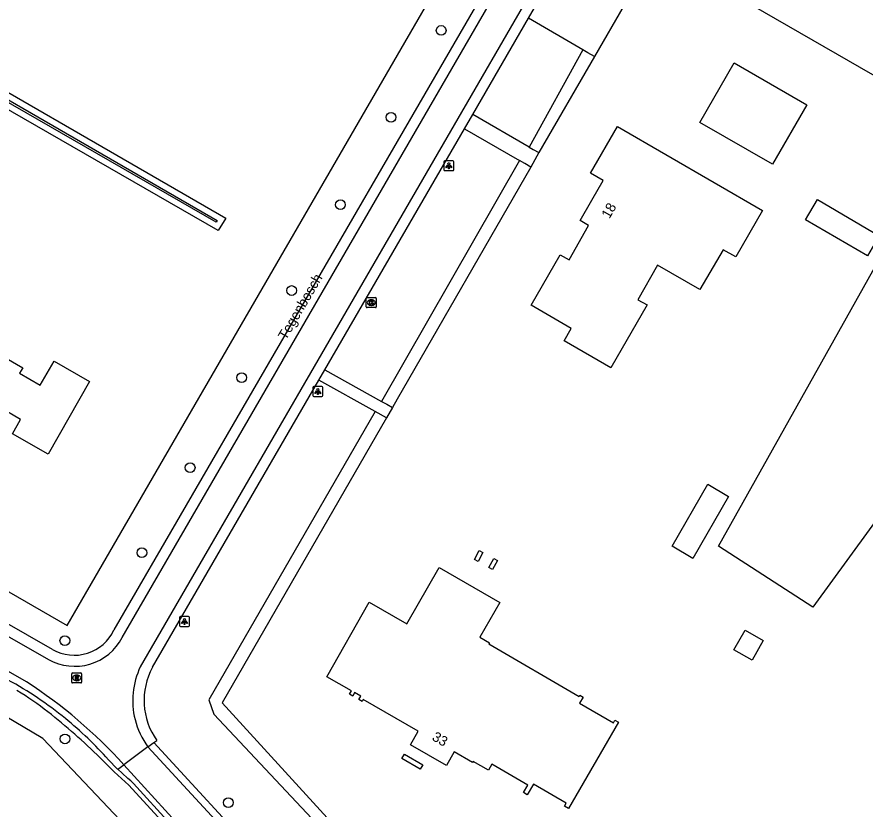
# Model space of a CAD drawing. Extents: x 156502 to 159074, y 384229 to 386094.
# Drawn here: x 157152.4 to 157237.7, y 385707.8 to 385787.5 of the extents above; entities that cross this region are included whole.
import ezdxf

# ---------------------------------------------------------------- set-up
doc = ezdxf.new("R2010")
doc.units = 0
for name, color, linetype in [('IMGEO_Berm_groen', 7, 'Continuous'), ('IMGEO_Berm_open', 7, 'Continuous'), ('IMGEO_Boom', 7, 'Continuous'), ('IMGEO_Erf', 7, 'Continuous'), ('IMGEO_Gemengd_bos', 7, 'Continuous'), ('IMGEO_Grasland_overig', 7, 'Continuous'), ('IMGEO_Groenvoorziening', 7, 'Continuous'), ('IMGEO_Hek', 7, 'Continuous'), ('IMGEO_Kolk', 7, 'Continuous'), ('IMGEO_Lichtpunt', 7, 'Continuous'), ('IMGEO_Openbare_ruimte_label', 7, 'Continuous'), ('IMGEO_Pand', 7, 'Continuous'), ('IMGEO_Pand_nummerreeks', 7, 'Continuous'), ('IMGEO_Rijbaan_lokaal_gesloten', 7, 'Continuous'), ('IMGEO_Rijbaan_lokaal_halfverhard', 7, 'Continuous'), ('IMGEO_Rijbaan_lokaal_open', 7, 'Continuous'), ('IMGEO_Rioolput', 7, 'Continuous'), ('IMGEO_Voetpad_open', 7, 'Continuous'), ('IMGEO_Waterloop', 7, 'Continuous')]:
    doc.layers.add(name, color=color, linetype=linetype)

msp = doc.modelspace()

# ---------------------------------------------------------------- linework, layer by layer
at = {"layer": 'IMGEO_Berm_groen'}
msp.add_lwpolyline([(157149.855, 385730.69), (157157.489, 385726.3), (157201.732, 385802.693)], dxfattribs=at)
at = {"layer": 'IMGEO_Berm_open'}
msp.add_lwpolyline([(157165.011, 385703.658), (157167.069, 385705.548), (157167.262, 385706.33), (157166.599, 385707.057), (157163.676, 385710.253), (157162.212, 385711.565), (157160.802, 385712.985)], dxfattribs=at)
for centre, radius, start, end in [((157139.852, 385698.063), 25.067, 51.20506, 59.86057), ((157114.204, 385665.314), 66.663, 45.65222, 51.65962)]:
    msp.add_arc(centre, radius, start, end, dxfattribs=at)
at = {"layer": 'IMGEO_Boom'}
for centre in [(157195.082, 385786.106), (157190.045, 385777.377), (157184.958, 385768.592), (157180.048, 385759.963), (157175.016, 385751.204), (157169.847, 385742.161), (157164.994, 385733.609), (157157.253, 385724.77), (157157.263, 385714.892), (157173.691, 385708.485)]:
    msp.add_circle(centre, 0.489, dxfattribs=at)
at = {"layer": 'IMGEO_Erf'}
msp.add_lwpolyline([(157069.688, 385879.771), (157062.244, 385869.451), (157047.224, 385849.55), (157042.786, 385843.67), (157065.314, 385829.887), (157068.346, 385827.983), (157173.435, 385767.228), (157172.677, 385766.006), (157064.372, 385828.327), (157041.356, 385841.775), (157036.588, 385835.458)], dxfattribs=at)
at = {"layer": 'IMGEO_Gemengd_bos'}
msp.add_lwpolyline([(157300.611, 385725.628), (157250.886, 385753.432), (157232.436, 385728.117), (157222.966, 385734.271), (157242.958, 385769.961), (157246.925, 385776.791)], dxfattribs=at)
at = {"layer": 'IMGEO_Grasland_overig'}
msp.add_lwpolyline([(157246.925, 385776.791), (157216.71, 385794.202)], dxfattribs=at)
at = {"layer": 'IMGEO_Groenvoorziening'}
for points in [[(157209.322, 385784.15), (157203.918, 385774.387)], [(157210.483, 385783.472), (157204.894, 385773.824)], [(157202.954, 385773.026), (157189.099, 385748.819)], [(157204.086, 385772.373), (157190.66, 385749.032), (157190.191, 385748.219)], [(157188.458, 385747.796), (157171.716, 385718.804), (157172.234, 385717.388), (157187.763, 385700.816)], [(157189.585, 385747.166), (157173.064, 385718.503), (157188.558, 385701.554)], [(157165.17, 385704.25), (157155.054, 385714.92), (157136.059, 385726.15)]]:
    msp.add_lwpolyline(points, dxfattribs=at)
at = {"layer": 'IMGEO_Hek'}
msp.add_lwpolyline([(157149.855, 385730.69), (157157.489, 385726.3), (157201.732, 385802.693)], dxfattribs=at)
at = {"layer": 'IMGEO_Kolk'}
for p, q in [((157187.556, 385758.32), (157187.556, 385759.172)), ((157187.631, 385759.246), (157188.483, 385759.246)), ((157188.044, 385759.026), (157188.069, 385759.026)), ((157188.557, 385759.172), (157188.557, 385758.32)), ((157188.483, 385758.246), (157187.631, 385758.246)), ((157188.067, 385758.466), (157188.042, 385758.466))]:
    msp.add_line(p, q, dxfattribs=at)
for points in [[(157187.556, 385758.32), (157187.556, 385759.172)], [(157187.631, 385759.246), (157188.483, 385759.246)], [(157187.877, 385758.946), (157188, 385758.946), (157188, 385758.795), (157188.13, 385758.946), (157188.294, 385758.946), (157188.148, 385758.795), (157188.301, 385758.546), (157188.149, 385758.546), (157188.064, 385758.71), (157188, 385758.643), (157188, 385758.546), (157187.877, 385758.546), (157187.877, 385758.946)], [(157188.557, 385759.172), (157188.557, 385758.32)], [(157188.483, 385758.246), (157187.631, 385758.246)]]:
    msp.add_lwpolyline(points, dxfattribs=at)
for centre, start, end in [((157187.633, 385759.17), 91.55205, 178.44795), ((157187.633, 385759.17), 91.55205, 178.44795), ((157188.481, 385759.17), 1.55205, 88.44795), ((157188.481, 385759.17), 1.55205, 88.44795), ((157187.633, 385758.322), 181.55205, 268.44795), ((157187.633, 385758.322), 181.55205, 268.44795), ((157188.481, 385758.322), 271.55205, 358.44795), ((157188.481, 385758.322), 271.55205, 358.44795)]:
    msp.add_arc(centre, 0.0765, start, end, dxfattribs=at)
for centre, major_axis, ratio, start_param, end_param in [((157188.043, 385758.746), (-0.387, 0.002), 0.722429, 4.712389, 7.853982), ((157188.068, 385758.746), (-0.39, 0.002), 0.717154, 1.570796, 4.712389)]:
    msp.add_ellipse(centre, major_axis=major_axis, ratio=ratio, start_param=start_param, end_param=end_param, dxfattribs=at)
at = {"layer": 'IMGEO_Lichtpunt'}
for p, q in [((157195.359, 385772.915), (157195.359, 385772.108)), ((157195.359, 385772.915), (157195.359, 385772.108)), ((157196.261, 385773.01), (157195.453, 385773.01)), ((157196.261, 385773.01), (157195.453, 385773.01)), ((157196.355, 385772.108), (157196.355, 385772.915)), ((157196.355, 385772.108), (157196.355, 385772.915)), ((157195.453, 385772.014), (157196.261, 385772.014)), ((157195.453, 385772.014), (157196.261, 385772.014)), ((157182.182, 385750.221), (157182.182, 385749.414)), ((157182.182, 385750.221), (157182.182, 385749.414)), ((157183.084, 385750.316), (157182.276, 385750.316)), ((157183.084, 385750.316), (157182.276, 385750.316)), ((157183.178, 385749.414), (157183.178, 385750.221)), ((157183.178, 385749.414), (157183.178, 385750.221)), ((157182.276, 385749.32), (157183.084, 385749.32)), ((157182.276, 385749.32), (157183.084, 385749.32)), ((157169.681, 385727.199), (157168.873, 385727.199)), ((157169.681, 385727.199), (157168.873, 385727.199)), ((157168.779, 385727.104), (157168.779, 385726.297)), ((157168.779, 385727.104), (157168.779, 385726.297)), ((157169.775, 385726.297), (157169.775, 385727.104)), ((157169.775, 385726.297), (157169.775, 385727.104)), ((157168.873, 385726.203), (157169.681, 385726.203)), ((157168.873, 385726.203), (157169.681, 385726.203))]:
    msp.add_line(p, q, dxfattribs=at)
for points in [[(157195.733, 385772.579), (157195.772, 385772.551), (157195.584, 385772.289), (157195.546, 385772.316), (157195.733, 385772.579)], [(157195.835, 385772.531), (157195.882, 385772.531), (157195.882, 385772.209), (157195.835, 385772.209), (157195.835, 385772.531)], [(157195.945, 385772.551), (157195.983, 385772.578), (157196.17, 385772.316), (157196.131, 385772.288), (157195.945, 385772.551)], [(157182.556, 385749.885), (157182.595, 385749.857), (157182.407, 385749.595), (157182.369, 385749.622), (157182.556, 385749.885)], [(157182.658, 385749.837), (157182.705, 385749.837), (157182.705, 385749.515), (157182.658, 385749.515), (157182.658, 385749.837)], [(157182.768, 385749.857), (157182.806, 385749.884), (157182.993, 385749.622), (157182.954, 385749.594), (157182.768, 385749.857)], [(157169.153, 385726.768), (157169.192, 385726.74), (157169.004, 385726.478), (157168.966, 385726.505), (157169.153, 385726.768)], [(157169.255, 385726.72), (157169.302, 385726.72), (157169.302, 385726.398), (157169.255, 385726.398), (157169.255, 385726.72)], [(157169.365, 385726.74), (157169.403, 385726.767), (157169.59, 385726.505), (157169.551, 385726.477), (157169.365, 385726.74)]]:
    msp.add_lwpolyline(points, dxfattribs=at)
for centre in [(157195.858, 385772.713), (157182.681, 385750.019), (157169.278, 385726.902)]:
    msp.add_circle(centre, 0.0994, dxfattribs=at)
for centre, start, end in [((157195.453, 385772.915), 90, 180), ((157195.453, 385772.915), 90, 180), ((157196.261, 385772.915), 0, 90), ((157196.261, 385772.915), 0, 90), ((157195.453, 385772.108), 180, 270), ((157195.453, 385772.108), 180, 270), ((157196.261, 385772.108), 270, 0), ((157196.261, 385772.108), 270, 360), ((157182.276, 385750.221), 90, 180), ((157182.276, 385750.221), 90, 180), ((157183.084, 385750.221), 0, 90), ((157183.084, 385750.221), 0, 90), ((157182.276, 385749.414), 180, 270), ((157182.276, 385749.414), 180, 270), ((157183.084, 385749.414), 270, 0), ((157183.084, 385749.414), 270, 360), ((157168.873, 385727.104), 90, 180), ((157168.873, 385727.104), 90, 180), ((157169.681, 385727.104), 0, 90), ((157169.681, 385727.104), 0, 90), ((157168.873, 385726.297), 180, 270), ((157168.873, 385726.297), 180, 270), ((157169.681, 385726.297), 270, 0), ((157169.681, 385726.297), 270, 360)]:
    msp.add_arc(centre, 0.0946, start, end, dxfattribs=at)
at = {"layer": 'IMGEO_Pand'}
for points in [[(157221.093, 385776.863), (157224.521, 385782.839), (157231.836, 385778.642), (157228.378, 385772.656), (157221.093, 385776.863)], [(157216.825, 385762.498), (157214.836, 385759.028), (157215.782, 385758.513), (157212.125, 385752.188), (157207.442, 385754.89), (157208.164, 385756.155), (157204.143, 385758.489), (157207.06, 385763.557), (157207.934, 385763.062), (157209.905, 385766.51), (157209.04, 385767.011), (157210.228, 385769.058), (157211.364, 385771.036), (157210.092, 385771.773), (157212.805, 385776.435), (157227.391, 385767.994), (157224.692, 385763.333), (157223.414, 385764.038), (157221.09, 385760.054), (157216.825, 385762.498)], [(157231.699, 385767.058), (157232.896, 385769.122), (157239.12, 385765.475), (157237.934, 385763.435), (157231.699, 385767.058)], [(157145.011, 385756.807), (157153.044, 385752.202), (157152.682, 385751.64), (157154.769, 385750.435), (157156.174, 385752.869), (157159.745, 385750.827), (157155.568, 385743.525), (157151.995, 385745.568), (157152.803, 385746.981), (157150.715, 385748.193), (157146.759, 385741.271), (157143.69, 385743.027), (157143.418, 385742.572), (157142.025, 385743.36), (157142.291, 385743.83), (157136.743, 385747.004), (157136.902, 385747.281), (157138.903, 385746.106), (157145.011, 385756.807)], [(157220.393, 385733.029), (157218.292, 385734.263), (157221.885, 385740.491), (157223.982, 385739.254), (157220.393, 385733.029)], [(157198.789, 385732.728), (157198.416, 385732.933), (157198.908, 385733.827), (157199.28, 385733.622), (157198.789, 385732.728)], [(157200.256, 385731.922), (157199.883, 385732.127), (157200.374, 385733.02), (157200.747, 385732.816), (157200.256, 385731.922)], [(157212.394, 385716.506), (157212.545, 385716.767), (157212.9, 385716.561), (157207.88, 385707.905), (157207.492, 385708.134), (157207.663, 385708.425), (157204.36, 385710.352), (157203.719, 385709.283), (157203.343, 385709.503), (157203.783, 385710.251), (157200.181, 385712.353), (157199.832, 385711.755), (157198.312, 385712.63), (157198.242, 385712.509), (157196.392, 385713.576), (157195.606, 385712.212), (157191.984, 385714.299), (157192.772, 385715.665), (157187.236, 385718.855), (157187.126, 385718.663), (157186.796, 385718.851), (157186.992, 385719.194), (157186.385, 385719.542), (157186.189, 385719.199), (157185.859, 385719.388), (157186.052, 385719.726), (157183.587, 385721.136), (157187.86, 385728.639), (157191.62, 385726.449), (157194.896, 385732.112), (157200.992, 385728.586), (157198.967, 385725.104), (157199.927, 385724.546), (157199.867, 385724.443), (157208.946, 385719.168), (157209.006, 385719.272), (157209.343, 385719.076), (157208.997, 385718.479), (157212.394, 385716.506)], [(157226.329, 385722.821), (157224.512, 385723.852), (157225.627, 385725.817), (157227.444, 385724.787), (157226.329, 385722.821)], [(157192.972, 385711.834), (157191.144, 385712.919), (157191.405, 385713.359), (157193.232, 385712.273), (157192.972, 385711.834)]]:
    msp.add_lwpolyline(points, dxfattribs=at)
at = {"layer": 'IMGEO_Rijbaan_lokaal_gesloten'}
for points in [[(157163.025, 385725.068), (157209.184, 385804.754)], [(157211.808, 385803.246), (157164.84, 385722.131)], [(157042.417, 385787.656), (157155.604, 385722.866)], [(157153.385, 385720.619), (157047.474, 385781.289)], [(157165.598, 385714.094), (157163.176, 385712.295)]]:
    msp.add_lwpolyline(points, dxfattribs=at)
for centre, radius, start, end in [((157158.231, 385727.619), 5.431, 241.07519, 331.97874), ((157171.922, 385718.745), 7.85, 154.44814, 194.01694), ((157126.977, 385679.637), 48.753, 42.05634, 57.20338), ((157171.939, 385718.751), 7.867, 194.03127, 216.29872)]:
    msp.add_arc(centre, radius, start, end, dxfattribs=at)
at = {"layer": 'IMGEO_Rijbaan_lokaal_halfverhard'}
for points in [[(157204.517, 385807.457), (157205.798, 385801.093), (157162.191, 385725.838)], [(157156.009, 385723.887), (157148.433, 385728.196)], [(157182.888, 385696.288), (157177.304, 385702.459), (157166.189, 385714.515)], [(157161.64, 385712.801), (157162.514, 385711.888), (157162.571, 385711.837)], [(157162.571, 385711.837), (157163.176, 385712.295)], [(157167.865, 385706.331), (157164.162, 385710.397), (157163.893, 385710.681), (157163.596, 385710.912), (157163.015, 385711.443), (157162.571, 385711.837)]]:
    msp.add_lwpolyline(points, dxfattribs=at)
for centre, radius, start, end in [((157158.202, 385727.709), 4.406, 240.15556, 334.87517), ((157132.493, 385686.215), 39.499, 51.08239, 61.14287), ((157131.825, 385685.972), 40.109, 41.98216, 50.5579)]:
    msp.add_arc(centre, radius, start, end, dxfattribs=at)
at = {"layer": 'IMGEO_Rijbaan_lokaal_open'}
for points in [[(157203.866, 385787.336), (157206.888, 385792.553)], [(157213.481, 385788.661), (157210.483, 385783.472)], [(157198.256, 385777.654), (157203.866, 385787.336)], [(157209.322, 385784.15), (157203.866, 385787.336)], [(157210.483, 385783.472), (157209.828, 385783.854), (157209.322, 385784.15)], [(157197.423, 385776.216), (157198.256, 385777.654)], [(157183.392, 385751.998), (157197.423, 385776.216)], [(157182.79, 385750.96), (157183.392, 385751.998)], [(157166.062, 385722.087), (157182.79, 385750.96)], [(157165.598, 385714.094), (157166.189, 385714.515)], [(157166.189, 385714.515), (157166.5, 385714.736)], [(157182.361, 385695.797), (157176.77, 385701.976), (157165.598, 385714.094)], [(157163.176, 385712.295), (157169.409, 385705.442), (157178.854, 385695.127), (157187.603, 385685.561), (157189.594, 385683.36)]]:
    msp.add_lwpolyline(points, dxfattribs=at)
msp.add_arc((157172.15, 385718.761), 6.937, 151.35104, 215.46869, dxfattribs=at)
at = {"layer": 'IMGEO_Rioolput'}
for p, q in [((157157.94, 385720.593), (157157.94, 385721.445)), ((157158.015, 385721.519), (157158.867, 385721.519)), ((157158.428, 385721.299), (157158.453, 385721.299)), ((157158.941, 385721.445), (157158.941, 385720.593)), ((157158.867, 385720.519), (157158.015, 385720.519)), ((157158.451, 385720.739), (157158.426, 385720.739))]:
    msp.add_line(p, q, dxfattribs=at)
for points in [[(157157.94, 385720.593), (157157.94, 385721.445)], [(157158.015, 385721.519), (157158.867, 385721.519)], [(157158.529, 385721.217), (157158.277, 385721.219), (157158.277, 385720.819)], [(157158.941, 385721.445), (157158.941, 385720.593)], [(157158.867, 385720.519), (157158.015, 385720.519)], [(157158.277, 385720.819), (157158.401, 385720.819), (157158.401, 385720.981), (157158.412, 385720.981)], [(157158.455, 385721.138), (157158.401, 385721.138), (157158.401, 385721.057)], [(157158.401, 385721.057), (157158.453, 385721.057)], [(157158.459, 385720.952), (157158.53, 385720.819), (157158.67, 385720.819), (157158.605, 385720.945)]]:
    msp.add_lwpolyline(points, dxfattribs=at)
for centre, radius, start, end in [((157158.017, 385721.443), 0.0765, 91.55205, 178.44795), ((157158.017, 385721.443), 0.0765, 91.55205, 178.44795), ((157158.528, 385721.107), 0.109, 350.36119, 89.41601), ((157158.865, 385721.443), 0.0765, 1.55205, 88.44795), ((157158.865, 385721.443), 0.0765, 1.55205, 88.44795), ((157158.017, 385720.595), 0.0765, 181.55205, 268.44795), ((157158.017, 385720.595), 0.0765, 181.55205, 268.44795), ((157158.411, 385720.928), 0.0533, 26.02933, 88.69889), ((157158.437, 385721.246), 0.19, 274.7715, 282.96867), ((157158.461, 385721.042), 0.0964, 77.00612, 93.18647), ((157158.475, 385721.099), 0.0378, 276.66336, 79.67722), ((157158.526, 385721.107), 0.112, 277.58423, 350.98172), ((157158.51, 385720.892), 0.108, 29.51342, 73.79051), ((157158.865, 385720.595), 0.0765, 271.55205, 358.44795), ((157158.865, 385720.595), 0.0765, 271.55205, 358.44795)]:
    msp.add_arc(centre, radius, start, end, dxfattribs=at)
for centre, major_axis, ratio, start_param, end_param in [((157158.427, 385721.019), (-0.387, 0.002), 0.722429, 4.712389, 7.853982), ((157158.452, 385721.019), (-0.39, 0.002), 0.717154, 1.570796, 4.712389)]:
    msp.add_ellipse(centre, major_axis=major_axis, ratio=ratio, start_param=start_param, end_param=end_param, dxfattribs=at)
at = {"layer": 'IMGEO_Voetpad_open'}
for points in [[(157203.918, 385774.387), (157198.256, 385777.654)], [(157197.423, 385776.216), (157202.954, 385773.026)], [(157203.918, 385774.387), (157204.337, 385774.145), (157204.894, 385773.824)], [(157204.894, 385773.824), (157204.086, 385772.373)], [(157204.086, 385772.373), (157203.479, 385772.723), (157202.954, 385773.026)], [(157183.392, 385751.998), (157189.099, 385748.819)], [(157188.458, 385747.796), (157182.79, 385750.96)], [(157189.099, 385748.819), (157189.61, 385748.533), (157190.191, 385748.219)], [(157189.585, 385747.166), (157188.458, 385747.796)], [(157190.191, 385748.219), (157189.585, 385747.166)]]:
    msp.add_lwpolyline(points, dxfattribs=at)
at = {"layer": 'IMGEO_Waterloop'}
msp.add_lwpolyline([(157064.986, 385829.358), (157068.025, 385827.45), (157172.568, 385767.011), (157172.466, 385766.846), (157064.684, 385828.865)], dxfattribs=at)

# ---------------------------------------------------------------- texts
at = {"layer": 'IMGEO_Openbare_ruimte_label'}
msp.add_text('Tegenbosch', height=1, rotation=59.79307, dxfattribs=at).set_placement((157179.489, 385754.913))
at = {"layer": 'IMGEO_Pand_nummerreeks'}
for s, rotation, p in [('18', 60.13192, (157211.993, 385767.111)), ('33', 330.0515, (157194.083, 385714.821))]:
    msp.add_text(s, height=1, rotation=rotation, dxfattribs=at).set_placement(p)

doc.saveas('drawing.dxf')
